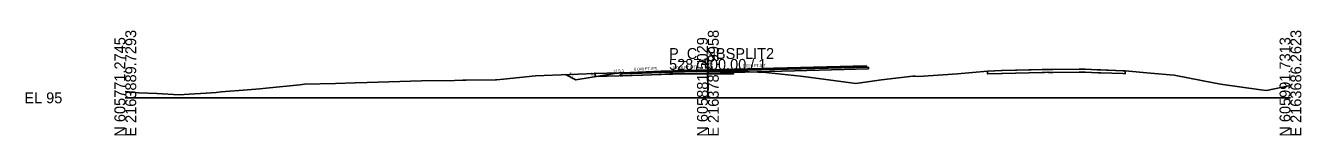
# Model space of a CAD drawing. Extents: x -26 to 1303, y -10 to 12038.
# Drawn here: x -25.7 to 302.8, y 3990.3 to 4017.3 of the extents above; entities that cross this region are included whole.
import ezdxf

# ---------------------------------------------------------------- set-up
doc = ezdxf.new("R2010")
doc.units = 0
for name, color, linetype in [('RD_GPK_XS_Cell', 7, 'Continuous'), ('RD_XS_Base', 7, 'Continuous'), ('RD_XS_ExGround', 7, 'Continuous'), ('RD_XS_ExPaveRet', 7, 'Continuous'), ('RD_XS_Greenside', 7, 'Continuous'), ('RD_XS_Pave', 7, 'Continuous'), ('RD_XS_PaveOvlay_CP', 7, 'Continuous'), ('RD_XS_TieSlope', 7, 'Continuous'), ('RD_XS_TX_Elev_EX', 7, 'Continuous'), ('RD_XS_TX_Elev_PR', 7, 'Continuous'), ('RD_XS_TX_ShdSlope', 7, 'Continuous'), ('RD_XS_TX_Slope', 7, 'Continuous')]:
    doc.layers.add(name, color=color, linetype=linetype)

msp = doc.modelspace()

# ---------------------------------------------------------------- linework, layer by layer
at = {"layer": 'RD_GPK_XS_Cell'}
for p, q in [((150, 4000), (150, 4010)), ((0, 4000), (150, 4000)), ((150, 4000), (300, 4000))]:
    msp.add_line(p, q, dxfattribs=at)
at = {"layer": 'RD_XS_Base'}
for p, q in [((128, 4006.13), (127.5, 4006.11)), ((127.5, 4006.11), (127.5, 4006.11)), ((127.5, 4006.11), (127.5, 4005.61)), ((127.5, 4005.61), (128, 4005.63)), ((138, 4006.53), (128, 4006.13)), ((128, 4006.13), (128, 4006.13)), ((128, 4005.63), (138, 4006.03)), ((128, 4005.63), (128, 4005.63)), ((150, 4006.84), (138, 4006.53)), ((138, 4006.53), (138, 4006.53)), ((138, 4006.03), (150, 4006.34)), ((138, 4006.03), (138, 4006.03)), ((150, 4006.84), (191.32, 4007.92)), ((191.32, 4007.42), (150, 4006.34)), ((150, 4006.34), (150, 4007)), ((150, 4007), (150, 4007)), ((150, 4007), (150, 4007)), ((150, 4007), (150, 4006.84)), ((150, 4006.84), (150, 4006.84)), ((150, 4006.34), (150, 4006.84)), ((150, 4006.84), (150, 4006.84)), ((150, 4006.84), (150, 4006.84)), ((150, 4006.34), (150, 4006.34)), ((174, 4007.47), (174, 4007.47)), ((174, 4007.47), (174, 4007.47)), ((174, 4006.97), (174, 4006.97)), ((174, 4006.97), (174, 4006.97)), ((190.82, 4007.9), (190.82, 4007.9)), ((191.32, 4007.92), (191.32, 4007.42)), ((191.32, 4007.88), (191.32, 4007.88))]:
    msp.add_line(p, q, dxfattribs=at)
at = {"layer": 'RD_XS_ExGround'}
msp.add_lwpolyline([(0, 4001.62), (3.36, 4001.29), (8.16, 4001.08), (13.86, 4000.78), (16.4, 4000.91), (20.8, 4001.24), (23.37, 4001.41), (24.66, 4001.5), (31.46, 4002.05), (34.67, 4002.31), (36.27, 4002.5), (44.92, 4003.37), (46.14, 4003.49), (54.13, 4003.66), (59.2, 4003.82), (62.31, 4003.91), (76.24, 4004.36), (84.74, 4004.49), (86.91, 4004.54), (87.75, 4004.55), (95.35, 4004.64), (95.55, 4004.65), (97.37, 4004.83), (105.65, 4005.64), (107.84, 4005.75), (120.97, 4006.26), (133.22, 4006.62), (137.55, 4006.76), (140.18, 4006.88), (140.53, 4006.89), (141.01, 4006.89), (142.66, 4006.89), (156.56, 4006.88), (164.91, 4006.51), (165.68, 4006.44), (173.88, 4005.56), (175.95, 4005.28), (188.08, 4003.66), (194.7, 4004.59), (202.73, 4005.57), (203.4, 4005.54), (204.26, 4005.47), (208.03, 4005.77), (214.25, 4006.21), (222.02, 4006.88), (225.73, 4007.03), (237.05, 4007.27), (237.63, 4007.3), (237.75, 4007.29), (238.09, 4007.29), (245.75, 4007.37), (247.15, 4007.36), (250.21, 4007.22), (257.46, 4006.96), (263.94, 4006.36), (270.04, 4005.83), (277.49, 4004.36), (282.02, 4003.5), (292.37, 4002.08), (293.83, 4001.86), (300, 4003.21)], dxfattribs=at)
at = {"layer": 'RD_XS_ExPaveRet'}
for points in [[(156.56, 4006.88), (156.56, 4006.88), (156.56, 4006.13), (156.56, 4006.13), (156.56, 4006.13), (142.66, 4006.14), (142.66, 4006.14), (141.01, 4006.14), (141.01, 4006.14), (140.53, 4006.14), (140.18, 4006.13), (140.18, 4006.13), (137.55, 4006.01), (137.55, 4006.01), (133.22, 4005.87), (133.22, 4005.87), (120.97, 4005.51), (120.97, 4005.51), (120.97, 4006.26), (120.97, 4006.26), (120.97, 4006.26), (133.22, 4006.62), (133.22, 4006.62), (137.55, 4006.76), (137.55, 4006.76), (140.18, 4006.88), (140.18, 4006.88), (140.53, 4006.89), (141.01, 4006.89), (141.01, 4006.89), (142.66, 4006.89), (142.66, 4006.89), (156.56, 4006.88), (156.56, 4006.88), (156.56, 4006.88)], [(156.56, 4006.88), (142.66, 4006.89), (141.01, 4006.89), (140.53, 4006.89), (140.18, 4006.88), (137.55, 4006.76), (133.22, 4006.62), (120.97, 4006.26), (120.97, 4005.51), (133.22, 4005.87), (137.55, 4006.01), (140.18, 4006.13), (140.53, 4006.14), (141.01, 4006.14), (142.66, 4006.14), (156.56, 4006.13), (156.56, 4006.13), (156.56, 4006.88), (156.56, 4006.88)], [(257.46, 4006.96), (256.88, 4006.98), (251.15, 4007.19), (251.03, 4007.2), (250.41, 4007.22), (247.18, 4007.37), (245.72, 4007.37), (245.58, 4007.37), (245.56, 4007.37), (238.78, 4007.3), (238.28, 4007.3), (237.75, 4007.29), (237.75, 4007.29), (237.56, 4007.31), (237.56, 4007.31), (236.69, 4007.26), (236.58, 4007.26), (236.04, 4007.25), (225.73, 4007.03), (225.59, 4007.02), (222.02, 4006.88), (222.02, 4006.88), (222.02, 4006.88), (222.02, 4006.87), (222.02, 4006.13), (222.02, 4006.13), (222.02, 4006.13), (225.59, 4006.27), (225.73, 4006.28), (236.04, 4006.5), (236.58, 4006.51), (236.69, 4006.51), (237.56, 4006.56), (237.56, 4006.56), (237.75, 4006.54), (237.75, 4006.54), (238.28, 4006.55), (238.78, 4006.55), (245.56, 4006.62), (245.58, 4006.62), (245.72, 4006.62), (247.18, 4006.62), (250.41, 4006.47), (251.03, 4006.45), (251.15, 4006.44), (256.88, 4006.23), (257.46, 4006.21), (257.46, 4006.21), (257.46, 4006.86), (257.46, 4006.96), (257.46, 4006.96)], [(257.46, 4006.96), (256.88, 4006.98), (251.15, 4007.19), (251.03, 4007.2), (250.41, 4007.22), (247.18, 4007.37), (245.72, 4007.37), (245.58, 4007.37), (245.56, 4007.37), (238.78, 4007.3), (238.28, 4007.3), (237.75, 4007.29), (237.75, 4007.29), (237.56, 4007.31), (237.56, 4007.31), (236.69, 4007.26), (236.58, 4007.26), (236.04, 4007.25), (225.73, 4007.03), (225.59, 4007.02), (222.02, 4006.88), (222.02, 4006.88), (222.02, 4006.87), (222.02, 4006.13), (222.02, 4006.13), (225.59, 4006.27), (225.73, 4006.28), (236.04, 4006.5), (236.58, 4006.51), (236.69, 4006.51), (237.56, 4006.56), (237.56, 4006.56), (237.75, 4006.54), (237.75, 4006.54), (238.28, 4006.55), (238.78, 4006.55), (245.56, 4006.62), (245.58, 4006.62), (245.72, 4006.62), (247.18, 4006.62), (250.41, 4006.47), (251.03, 4006.45), (251.15, 4006.44), (256.88, 4006.23), (257.46, 4006.21), (257.46, 4006.86), (257.46, 4006.96)]]:
    msp.add_lwpolyline(points, dxfattribs=at)
at = {"layer": 'RD_XS_Greenside'}
for p, q in [((116, 4004.62), (113.32, 4005.96)), ((126, 4006.29), (116, 4004.62))]:
    msp.add_line(p, q, dxfattribs=at)
at = {"layer": 'RD_XS_Pave'}
for p, q in [((190.82, 4008.22), (150, 4007.16)), ((190.82, 4008.06), (190.82, 4008.22)), ((190.82, 4008.22), (190.82, 4008.22)), ((138, 4006.85), (128, 4006.45)), ((128, 4006.29), (138, 4006.69)), ((138, 4006.69), (128, 4006.29)), ((128, 4006.13), (138, 4006.53)), ((128, 4006.45), (128, 4006.45)), ((128, 4006.45), (128, 4006.29)), ((128, 4006.29), (128, 4006.29)), ((128, 4006.29), (128, 4006.13)), ((150, 4007.16), (138, 4006.85)), ((138, 4006.69), (150, 4007)), ((150, 4007), (138, 4006.69)), ((138, 4006.85), (138, 4006.85)), ((138, 4006.53), (150, 4006.84)), ((138, 4006.69), (138, 4006.69)), ((138, 4006.69), (138, 4006.69)), ((138, 4006.53), (138, 4006.53)), ((190.82, 4008.06), (150, 4007)), ((150, 4007), (190.82, 4008.06)), ((150, 4006.84), (190.82, 4007.9)), ((150, 4007.16), (150, 4007.16)), ((150, 4007), (150, 4007)), ((150, 4007), (150, 4007)), ((150, 4007), (150, 4006.84)), ((150, 4007), (150, 4007)), ((150, 4006.84), (150, 4007)), ((150, 4007), (150, 4007)), ((150, 4007), (150, 4007)), ((150, 4006.84), (150, 4006.84)), ((150, 4006.84), (150, 4006.84)), ((174, 4007.78), (174, 4007.78)), ((174, 4007.78), (174, 4007.78)), ((174, 4007.63), (174, 4007.63)), ((174, 4007.63), (174, 4007.63)), ((174, 4007.63), (174, 4007.63)), ((174, 4007.63), (174, 4007.63)), ((174, 4007.47), (174, 4007.47)), ((174, 4007.47), (174, 4007.47)), ((190.82, 4007.9), (190.82, 4008.06)), ((190.82, 4008.06), (190.82, 4008.06))]:
    msp.add_line(p, q, dxfattribs=at)
at = {"layer": 'RD_XS_PaveOvlay_CP'}
for p, q in [((190.82, 4008.22), (150, 4007.16)), ((138, 4006.85), (128, 4006.45)), ((150, 4007.16), (138, 4006.85)), ((138, 4006.85), (138, 4006.85)), ((150, 4007.16), (150, 4007.16)), ((174, 4007.78), (174, 4007.78)), ((174, 4007.78), (174, 4007.78))]:
    msp.add_line(p, q, dxfattribs=at)
at = {"layer": 'RD_XS_TieSlope'}
msp.add_line((128, 4006.45), (126, 4006.29), dxfattribs=at)

# ---------------------------------------------------------------- texts
at = {"layer": 'RD_GPK_XS_Cell'}
for s, p in [('N 605771.2745', (0, 3990)), ('E 2163889.7293', (2.8, 3990)), ('N 605881.5029', (150, 3990)), ('E 2163787.9958', (152.8, 3990)), ('N 605991.7313', (300, 3990)), ('E 2163686.2623', (302.8, 3990))]:
    msp.add_text(s, height=2.8, rotation=90, dxfattribs=at).set_placement(p)
for s, p in [('P_C_NBSPLIT2', (140, 4010)), ('5287+00.00 / 1', (140, 4007.2)), ('EL 95', (-26, 3998.6))]:
    msp.add_text(s, height=2.8, dxfattribs=at).set_placement(p)
at = {"layer": 'RD_XS_TX_Elev_EX'}
msp.add_text('101.89', height=0.6, rotation=90, dxfattribs=at).set_placement((149.65, 4007.76))
at = {"layer": 'RD_XS_TX_Elev_PR'}
msp.add_text('102.16', height=1, rotation=90, dxfattribs=at).set_placement((151.19, 4007.53))
at = {"layer": 'RD_XS_TX_ShdSlope'}
msp.add_text('12.5:1', height=0.75, rotation=4.5739, dxfattribs=at).set_placement((125.59, 4006.42))
at = {"layer": 'RD_XS_TX_Slope'}
for s, rotation, p in [('0.028 FT./FT.', 1.6039, (141, 4007.33)), ('0.028 FT./FT.', 1.6039, (159, 4007.83)), ('2:1', 333.4349, (114.08, 4006.04)), ('6:1', 9.4642, (119.89, 4005.68)), ('0.040 FT./FT.', 2.2906, (130.99, 4006.96))]:
    msp.add_text(s, height=0.75, rotation=rotation, dxfattribs=at).set_placement(p)

doc.saveas('drawing.dxf')
